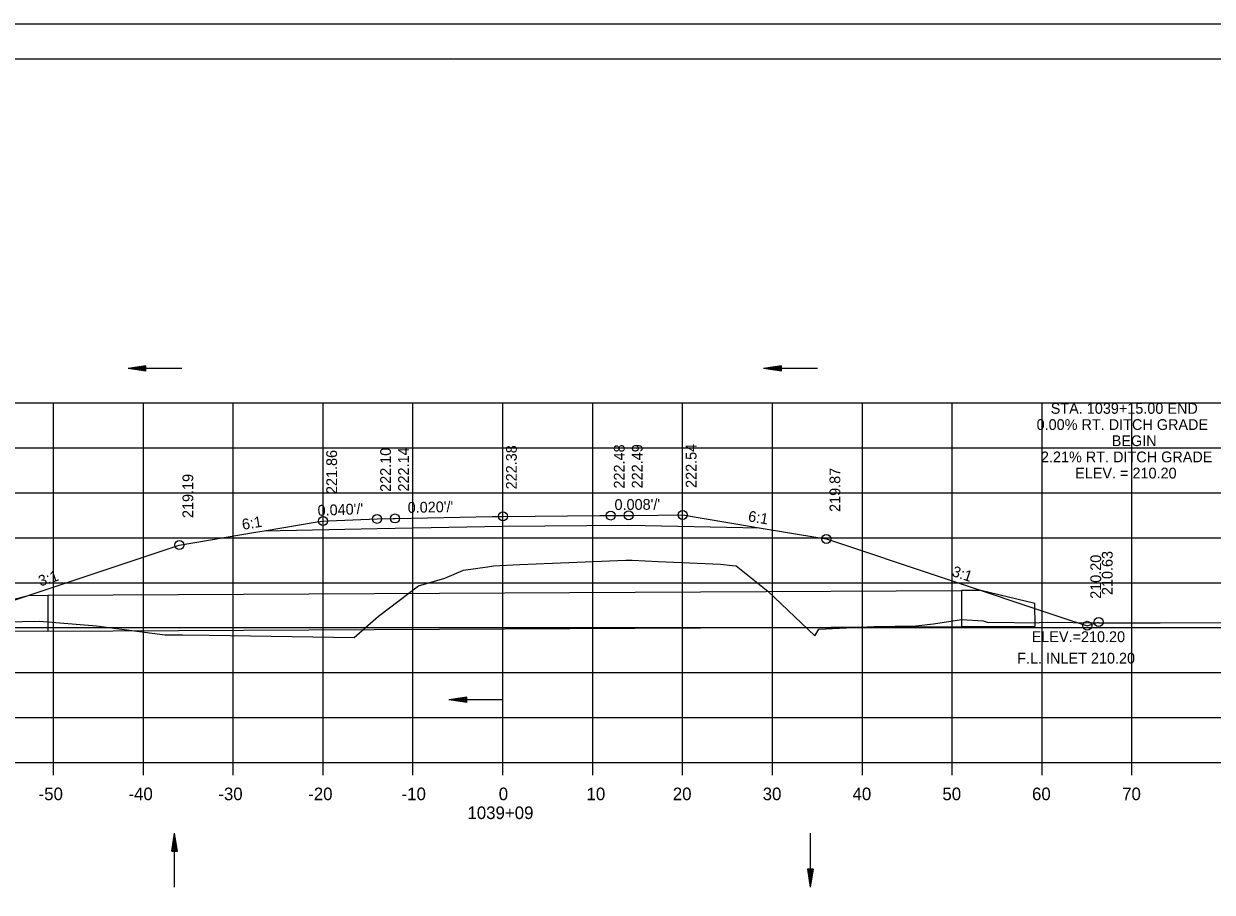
# Model space of a CAD drawing. Extents: x 1386544 to 1388153, y 379785 to 390999.
# Drawn here: x 1387306.4 to 1387438.6, y 386635.6 to 386732.2 of the extents above; entities that cross this region are included whole.
import ezdxf

# ---------------------------------------------------------------- set-up
doc = ezdxf.new("R2010")
doc.units = 0
for name, color, linetype in [('R_Alt Surface', 7, 'Continuous'), ('R_Axis', 7, 'Continuous'), ('R_Axis Annot', 7, 'Continuous'), ('R_Border', 7, 'Continuous'), ('R_Exist Surface', 7, 'Continuous'), ('R_Fin Surface', 7, 'Continuous'), ('R_Grid', 7, 'Continuous'), ('R_No Plot', 7, 'Continuous'), ('R_Water', 7, 'Continuous'), ('R_Water Annot', 7, 'Continuous'), ('R_Xsect Elev', 7, 'Continuous'), ('R_Xsect Slope', 7, 'Continuous')]:
    doc.layers.add(name, color=color, linetype=linetype)

msp = doc.modelspace()

# ---------------------------------------------------------------- linework, layer by layer
at = {"layer": 'R_Alt Surface'}
msp.add_lwpolyline([(1387333.11, 386675.76), (1387345.68, 386676.01), (1387359.68, 386676.29), (1387373.68, 386676.4), (1387388.21, 386676.11)], dxfattribs=at)
at = {"layer": 'R_Axis'}
for p, q in [((1387209.68, 386650), (1387509.68, 386650)), ((1387309.68, 386648.6), (1387309.68, 386650)), ((1387319.68, 386648.6), (1387319.68, 386650)), ((1387329.68, 386648.6), (1387329.68, 386650)), ((1387339.68, 386648.6), (1387339.68, 386650)), ((1387349.68, 386648.6), (1387349.68, 386650)), ((1387359.68, 386648.6), (1387359.68, 386650)), ((1387369.68, 386648.6), (1387369.68, 386650)), ((1387379.68, 386648.6), (1387379.68, 386650)), ((1387389.68, 386648.6), (1387389.68, 386650)), ((1387399.68, 386648.6), (1387399.68, 386650)), ((1387409.68, 386648.6), (1387409.68, 386650)), ((1387419.68, 386648.6), (1387419.68, 386650)), ((1387429.68, 386648.6), (1387429.68, 386650))]:
    msp.add_line(p, q, dxfattribs=at)
at = {"layer": 'R_Border'}
for p, q in [((1387201.68, 386728.28), (1387517.86, 386728.28)), ((1387354.2, 386728.02), (1387354.2, 386728.02)), ((1387354.2, 386728.02), (1387354.2, 386728.02))]:
    msp.add_line(p, q, dxfattribs=at)
at = {"layer": 'R_Exist Surface'}
msp.add_lwpolyline([(1387304.28, 386665.63), (1387308.11, 386665.7), (1387314.48, 386665.19), (1387322.06, 386664.21), (1387324.04, 386664.19), (1387327, 386664.15), (1387343.14, 386663.91), (1387345.83, 386666.29), (1387350.29, 386669.65), (1387353.23, 386670.49), (1387355.29, 386671.4), (1387357.98, 386671.78), (1387358.62, 386671.89), (1387361.57, 386672.03), (1387373.36, 386672.5), (1387374.06, 386672.49), (1387376.96, 386672.37), (1387379.59, 386672.26), (1387383.9, 386672.04), (1387385.19, 386671.9), (1387385.65, 386671.89), (1387389.18, 386669.05), (1387394.38, 386664.09), (1387394.82, 386664.81), (1387401, 386665.12), (1387405.63, 386665.21), (1387407.59, 386665.41), (1387410.7, 386665.92), (1387413.11, 386665.75), (1387413.67, 386665.58), (1387413.88, 386665.6), (1387419.3, 386665.55), (1387419.4, 386665.58), (1387420.24, 386665.6), (1387426.01, 386665.53), (1387430.46, 386665.54), (1387432.82, 386665.55), (1387441.06, 386665.56)], dxfattribs=at)
at = {"layer": 'R_Fin Surface'}
msp.add_lwpolyline([(1387297.6, 386665.5), (1387323.68, 386674.19), (1387332.16, 386675.6), (1387333.11, 386675.76), (1387339.02, 386676.75), (1387339.68, 386676.86), (1387340.28, 386676.88), (1387345.68, 386677.1), (1387347.48, 386677.13), (1387347.68, 386677.14), (1387358.48, 386677.35), (1387359.68, 386677.38), (1387370.48, 386677.46), (1387371.68, 386677.47), (1387373.48, 386677.49), (1387373.68, 386677.49), (1387374.28, 386677.49), (1387379.68, 386677.54), (1387387.35, 386676.26), (1387388.21, 386676.11), (1387394.94, 386674.99), (1387395.68, 386674.87), (1387421.77, 386666.17), (1387424.7, 386665.2), (1387425.59, 386665.49), (1387425.98, 386665.62)], dxfattribs=at)
at = {"layer": 'R_Grid'}
for p, q in [((1387209.68, 386690), (1387509.68, 386690)), ((1387309.68, 386650), (1387309.68, 386690)), ((1387319.68, 386650), (1387319.68, 386690)), ((1387329.68, 386650), (1387329.68, 386690)), ((1387339.68, 386650), (1387339.68, 386690)), ((1387349.68, 386650), (1387349.68, 386690)), ((1387359.68, 386650), (1387359.68, 386690)), ((1387369.68, 386650), (1387369.68, 386690)), ((1387379.68, 386650), (1387379.68, 386690)), ((1387389.68, 386650), (1387389.68, 386690)), ((1387399.68, 386650), (1387399.68, 386690)), ((1387409.68, 386650), (1387409.68, 386690)), ((1387419.68, 386650), (1387419.68, 386690)), ((1387429.68, 386650), (1387429.68, 386690)), ((1387209.68, 386685), (1387509.68, 386685)), ((1387209.68, 386680), (1387509.68, 386680)), ((1387209.68, 386675), (1387509.68, 386675)), ((1387209.68, 386670), (1387509.68, 386670)), ((1387209.68, 386665), (1387509.68, 386665)), ((1387209.68, 386660), (1387509.68, 386660)), ((1387209.68, 386655), (1387509.68, 386655)), ((1387209.68, 386650), (1387509.68, 386650))]:
    msp.add_line(p, q, dxfattribs=at)
at = {"layer": 'R_No Plot'}
msp.add_line((1387189.28, 386732.18), (1387522.61, 386732.18), dxfattribs=at)
for points in [[(1387189.27, 386732.18), (1387522.61, 386732.18), (1387522.61, 386518.84), (1387189.27, 386518.84)], [(1387435.6, 386728.28), (1387455.22, 386728.28), (1387455.22, 386718.4), (1387471.33, 386718.4), (1387494.53, 386718.4), (1387494.53, 386694.07), (1387517.86, 386694.07), (1387517.86, 386522.82), (1387201.68, 386522.82), (1387201.68, 386728.28)]]:
    msp.add_lwpolyline(points, close=True, dxfattribs=at)
for centre in [(1387359.68, 386677.38), (1387371.68, 386677.47), (1387373.68, 386677.49), (1387379.68, 386677.54), (1387339.68, 386676.86), (1387345.68, 386677.1), (1387347.68, 386677.14), (1387395.68, 386674.87), (1387323.68, 386674.19), (1387425.98, 386665.62), (1387424.7, 386665.2)]:
    msp.add_circle(centre, 0.5, dxfattribs=at)
at = {"layer": 'R_Water'}
for p, q in [((1387319.97, 386694.12), (1387317.97, 386693.82)), ((1387319.97, 386694.12), (1387317.97, 386693.82)), ((1387323.97, 386693.82), (1387317.97, 386693.82)), ((1387319.97, 386693.52), (1387317.97, 386693.82)), ((1387319.97, 386693.52), (1387317.97, 386693.82)), ((1387319.97, 386694.07), (1387318.3, 386693.82)), ((1387319.97, 386694.07), (1387318.3, 386693.82)), ((1387319.97, 386693.57), (1387318.3, 386693.82)), ((1387319.97, 386693.57), (1387318.3, 386693.82)), ((1387319.97, 386694.02), (1387318.64, 386693.82)), ((1387319.97, 386694.02), (1387318.64, 386693.82)), ((1387319.97, 386693.62), (1387318.64, 386693.82)), ((1387319.97, 386693.62), (1387318.64, 386693.82)), ((1387319.97, 386693.97), (1387318.98, 386693.82)), ((1387319.97, 386693.97), (1387318.98, 386693.82)), ((1387319.97, 386693.67), (1387318.98, 386693.82)), ((1387319.97, 386693.67), (1387318.98, 386693.82)), ((1387319.97, 386693.92), (1387319.32, 386693.82)), ((1387319.97, 386693.92), (1387319.32, 386693.82)), ((1387319.97, 386693.72), (1387319.32, 386693.82)), ((1387319.97, 386693.72), (1387319.32, 386693.82)), ((1387319.97, 386693.87), (1387319.65, 386693.82)), ((1387319.97, 386693.87), (1387319.65, 386693.82)), ((1387319.97, 386693.77), (1387319.65, 386693.82)), ((1387319.97, 386693.77), (1387319.65, 386693.82)), ((1387319.97, 386693.52), (1387319.97, 386694.12)), ((1387319.97, 386693.52), (1387319.97, 386694.12)), ((1387390.7, 386694.12), (1387388.7, 386693.82)), ((1387390.7, 386694.12), (1387388.7, 386693.82)), ((1387394.7, 386693.82), (1387388.7, 386693.82)), ((1387390.7, 386693.52), (1387388.7, 386693.82)), ((1387390.7, 386693.52), (1387388.7, 386693.82)), ((1387390.7, 386694.07), (1387389.03, 386693.82)), ((1387390.7, 386694.07), (1387389.03, 386693.82)), ((1387390.7, 386693.57), (1387389.03, 386693.82)), ((1387390.7, 386693.57), (1387389.03, 386693.82)), ((1387390.7, 386694.02), (1387389.37, 386693.82)), ((1387390.7, 386694.02), (1387389.37, 386693.82)), ((1387390.7, 386693.62), (1387389.37, 386693.82)), ((1387390.7, 386693.62), (1387389.37, 386693.82)), ((1387390.7, 386693.97), (1387389.71, 386693.82)), ((1387390.7, 386693.97), (1387389.71, 386693.82)), ((1387390.7, 386693.67), (1387389.71, 386693.82)), ((1387390.7, 386693.67), (1387389.71, 386693.82)), ((1387390.7, 386693.92), (1387390.05, 386693.82)), ((1387390.7, 386693.92), (1387390.05, 386693.82)), ((1387390.7, 386693.72), (1387390.05, 386693.82)), ((1387390.7, 386693.72), (1387390.05, 386693.82)), ((1387390.7, 386693.87), (1387390.38, 386693.82)), ((1387390.7, 386693.87), (1387390.38, 386693.82)), ((1387390.7, 386693.77), (1387390.38, 386693.82)), ((1387390.7, 386693.77), (1387390.38, 386693.82)), ((1387390.7, 386693.52), (1387390.7, 386694.12)), ((1387390.7, 386693.52), (1387390.7, 386694.12)), ((1387309.04, 386668.6), (1387410.71, 386669.12)), ((1387309.06, 386664.6), (1387410.73, 386665.12)), ((1387355.66, 386657.25), (1387353.66, 386656.95)), ((1387355.66, 386657.25), (1387353.66, 386656.95)), ((1387359.66, 386656.95), (1387353.66, 386656.95)), ((1387355.66, 386656.65), (1387353.66, 386656.95)), ((1387355.66, 386656.65), (1387353.66, 386656.95)), ((1387355.66, 386657.2), (1387354, 386656.95)), ((1387355.66, 386657.2), (1387354, 386656.95)), ((1387355.66, 386656.7), (1387354, 386656.95)), ((1387355.66, 386656.7), (1387354, 386656.95)), ((1387355.66, 386657.15), (1387354.34, 386656.95)), ((1387355.66, 386657.15), (1387354.34, 386656.95)), ((1387355.66, 386656.75), (1387354.34, 386656.95)), ((1387355.66, 386656.75), (1387354.34, 386656.95)), ((1387355.66, 386657.1), (1387354.68, 386656.95)), ((1387355.66, 386657.1), (1387354.68, 386656.95)), ((1387355.66, 386656.8), (1387354.68, 386656.95)), ((1387355.66, 386656.8), (1387354.68, 386656.95)), ((1387355.66, 386657.05), (1387355.01, 386656.95)), ((1387355.66, 386657.05), (1387355.01, 386656.95)), ((1387355.66, 386656.85), (1387355.01, 386656.95)), ((1387355.66, 386656.85), (1387355.01, 386656.95)), ((1387355.66, 386657), (1387355.35, 386656.95)), ((1387355.66, 386657), (1387355.35, 386656.95)), ((1387355.66, 386656.9), (1387355.35, 386656.95)), ((1387355.66, 386656.9), (1387355.35, 386656.95)), ((1387355.66, 386656.65), (1387355.66, 386657.25)), ((1387355.66, 386656.65), (1387355.66, 386657.25)), ((1387322.86, 386640.13), (1387323.16, 386642.13)), ((1387322.86, 386640.13), (1387323.16, 386642.13)), ((1387322.91, 386640.13), (1387323.16, 386641.8)), ((1387322.91, 386640.13), (1387323.16, 386641.8)), ((1387322.97, 386640.13), (1387323.16, 386641.45)), ((1387322.97, 386640.13), (1387323.16, 386641.45)), ((1387323.02, 386640.13), (1387323.16, 386641.12)), ((1387323.02, 386640.13), (1387323.16, 386641.12)), ((1387323.16, 386636.13), (1387323.16, 386642.13)), ((1387323.46, 386640.13), (1387323.16, 386642.13)), ((1387323.46, 386640.13), (1387323.16, 386642.13)), ((1387323.41, 386640.13), (1387323.16, 386641.8)), ((1387323.41, 386640.13), (1387323.16, 386641.8)), ((1387323.36, 386640.13), (1387323.16, 386641.45)), ((1387323.36, 386640.13), (1387323.16, 386641.45)), ((1387323.31, 386640.13), (1387323.16, 386641.12)), ((1387323.31, 386640.13), (1387323.16, 386641.12)), ((1387393.89, 386642.13), (1387393.89, 386636.13)), ((1387322.86, 386640.13), (1387323.46, 386640.13)), ((1387322.86, 386640.13), (1387323.46, 386640.13)), ((1387323.07, 386640.13), (1387323.16, 386640.78)), ((1387323.07, 386640.13), (1387323.16, 386640.78)), ((1387323.12, 386640.13), (1387323.16, 386640.45)), ((1387323.12, 386640.13), (1387323.16, 386640.45)), ((1387323.26, 386640.13), (1387323.16, 386640.78)), ((1387323.26, 386640.13), (1387323.16, 386640.78)), ((1387323.21, 386640.13), (1387323.16, 386640.45)), ((1387323.21, 386640.13), (1387323.16, 386640.45)), ((1387393.59, 386638.13), (1387393.89, 386636.13)), ((1387394.19, 386638.13), (1387393.59, 386638.13)), ((1387393.59, 386638.13), (1387393.89, 386636.13)), ((1387394.19, 386638.13), (1387393.59, 386638.13)), ((1387393.64, 386638.13), (1387393.89, 386636.46)), ((1387393.64, 386638.13), (1387393.89, 386636.46)), ((1387393.7, 386638.13), (1387393.89, 386636.81)), ((1387393.7, 386638.13), (1387393.89, 386636.81)), ((1387393.75, 386638.13), (1387393.89, 386637.14)), ((1387393.75, 386638.13), (1387393.89, 386637.14)), ((1387393.8, 386638.13), (1387393.89, 386637.48)), ((1387393.8, 386638.13), (1387393.89, 386637.48)), ((1387393.85, 386638.13), (1387393.89, 386637.81)), ((1387393.85, 386638.13), (1387393.89, 386637.81)), ((1387394.19, 386638.13), (1387393.89, 386636.13)), ((1387393.99, 386638.13), (1387393.89, 386637.48)), ((1387394.09, 386638.13), (1387393.89, 386636.81)), ((1387394.14, 386638.13), (1387393.89, 386636.46)), ((1387394.04, 386638.13), (1387393.89, 386637.14)), ((1387393.94, 386638.13), (1387393.89, 386637.81)), ((1387394.19, 386638.13), (1387393.89, 386636.13)), ((1387393.99, 386638.13), (1387393.89, 386637.48)), ((1387394.09, 386638.13), (1387393.89, 386636.81)), ((1387394.14, 386638.13), (1387393.89, 386636.46)), ((1387394.04, 386638.13), (1387393.89, 386637.14)), ((1387393.94, 386638.13), (1387393.89, 386637.81))]:
    msp.add_line(p, q, dxfattribs=at)
for points in [[(1387309.04, 386668.6), (1387309.06, 386664.6), (1387300.89, 386664.56), (1387300.88, 386667.06), (1387306.87, 386668.59)], [(1387410.71, 386669.12), (1387410.73, 386665.12), (1387418.9, 386665.17), (1387418.89, 386667.67), (1387412.88, 386669.14)]]:
    msp.add_lwpolyline(points, close=True, dxfattribs=at)

# ---------------------------------------------------------------- texts
at = {"layer": 'R_Axis Annot'}
for s, p in [('-50', (1387308.02, 386645.8)), ('-40', (1387318.02, 386645.8)), ('-30', (1387328.02, 386645.8)), ('-20', (1387338.02, 386645.8)), ('-10', (1387348.41, 386645.8)), ('0', (1387359.22, 386645.8)), ('10', (1387368.99, 386645.8)), ('20', (1387378.59, 386645.8)), ('30', (1387388.59, 386645.8)), ('40', (1387398.59, 386645.8)), ('50', (1387408.59, 386645.8)), ('60', (1387418.56, 386645.8)), ('70', (1387428.59, 386645.8)), ('1039+09', (1387355.74, 386643.7))]:
    msp.add_text(s, height=1.4, dxfattribs=at).set_placement(p)
at = {"layer": 'R_Water Annot'}
msp.add_text('F.L. INLET 210.20', height=1.2, dxfattribs=at).set_placement((1387416.91, 386661))
at = {"layer": 'R_Xsect Elev'}
for s, p in [('STA. 1039+15.00 END', (1387420.64, 386688.79)), ('0.00% RT. DITCH GRADE', (1387419.07, 386686.99)), ('BEGIN', (1387427.43, 386685.19)), ('2.21% RT. DITCH GRADE', (1387419.55, 386683.39)), ('ELEV. = 210.20', (1387423.36, 386681.59)), ('ELEV.=210.20', (1387418.52, 386663.39))]:
    msp.add_text(s, height=1.2, dxfattribs=at).set_placement(p)
for s, p in [('221.86', (1387341.23, 386679.86)), ('222.10', (1387347.23, 386680.1)), ('222.14', (1387349.23, 386680.14)), ('222.38', (1387361.23, 386680.38)), ('222.48', (1387373.23, 386680.47)), ('222.49', (1387375.23, 386680.49)), ('222.54', (1387381.23, 386680.54)), ('219.19', (1387325.23, 386677.19)), ('219.87', (1387397.23, 386677.87)), ('210.20', (1387426.25, 386668.2)), ('210.63', (1387427.53, 386668.62))]:
    msp.add_text(s, height=1.2, rotation=90, dxfattribs=at).set_placement(p)
at = {"layer": 'R_Xsect Slope'}
for s, rotation, p in [("0.008'/'", 0.4583, (1387372.11, 386678.08)), ("0.040'/'", 2.2906, (1387339.09, 386677.43)), ("0.020'/'", 1.1458, (1387349.1, 386677.76)), ('6:1', 350.5377, (1387386.91, 386676.84)), ('6:1', 9.4623, (1387330.75, 386675.87)), ('3:1', 18.4349, (1387308.23, 386669.57)), ('3:1', 341.5651, (1387409.56, 386670.77))]:
    msp.add_text(s, height=1.2, rotation=rotation, dxfattribs=at).set_placement(p)

doc.saveas('drawing.dxf')
